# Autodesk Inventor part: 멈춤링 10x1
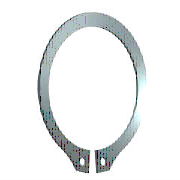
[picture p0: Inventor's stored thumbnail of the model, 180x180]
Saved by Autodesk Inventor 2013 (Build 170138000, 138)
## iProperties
IsCustomPart: 0
Created: 2015-11
Part Number: 멈춤링 10x1
Material: 스테인리스강
Description: 리테이닝 링(C형)
Document SubType Name: Modeling
Standard: KS B 1336
Designer: mdu
Standards Organization: KS
Language: ko-KR
Size Designation: 10 x 1
Categories: <MemberInstance><Categories><Category DisplayName="샤프트 부품" InternalName="7f7aeb1f-a693-4053-b835-cee3144e0d98" Mnemonic="SHFT"><Category DisplayName="써클립" Inter
Density: 8.08 g/cm^3
Mass: 0.434929 g
Surface Area: 1.9243 cm^2
Volume: 0.0538279 cm^3
Author: mdu
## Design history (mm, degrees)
sketch "스케치1"
  geometry: L1 (-6, 0)-(6, 0) reference; L2 (0, 20.189)-(0, -80.536) reference; L3 (-48.09, 0)-(48.09, 0) reference; L4 (-0.3, -9.791)-(-0.3, -12.791); L5 (-0.3, -6.54)-(-0.3, -13.29); L6 (-2.795, 1.6)-(3.672, 1.6); L7 (0.3, -6.54)-(0.3, -13.29); L8 (0.3, -9.791)-(0.3, -12.791); C1 r 0.6 at (-1.2, -11.486); C2 r 0.6 at (1.2, -11.486); A1 r 4.8 centre (0, -5) between (0.3, -9.791) and (-0.3, -9.791); A2 r 6.2 centre (0, -4.6) between (2.988, -10.033) and (-2.988, -10.033); A3 r 7.796 centre (0, -5) between (-1.418, -12.666) and (-0.3, -12.791); A4 r 1.2 centre (-1.2, -11.486) between (-2.383, -11.285) and (-1.418, -12.666); A5 r 1.2 centre (-3.566, -11.084) between (-2.383, -11.285) and (-2.988, -10.033); A6 r 1.2 centre (3.566, -11.084) between (2.988, -10.033) and (2.383, -11.285); A7 r 1.2 centre (1.2, -11.486) between (1.418, -12.666) and (2.383, -11.285); A8 r 7.796 centre (0, -5) between (0.3, -12.791) and (1.418, -12.666)
  constraints: 16 point on circle, 12 end point, 10 centre point, 9 symmetric about line, 5 point on line, 4 tangent, 3 coincident, 2 horizontal, 1 perpendicular, 1 vertical, 5 other
  dimensions: "d0" = 9.6 diameter of A1 (= ND); "d1" = 3 distance of L4.end L4.start (= SRB2); "d6" = 0.3 distance between parallel lines of L2 L5 (= 0.25 x SD5); "d7" = 1.6 distance between parallel lines of L6 L3 (= SRB1); "d8" = 0.4 distance of A1.centre A2.centre (= 0.25 x SRB1); "d9" = 1.2 radius of A4 (= SD5); "d10" = 1.2 radius of A5 (= SD5); "d11" = 0.9 distance from line of L4 A4.centre (= 0.75 x SD5); "d12" = 1.2 diameter of C1 (= SD5); "d13" = 1.2 diameter of C2 (= SD5); "d14" = 5 distance from line of A1.centre L1 (= 0.5 x WD)
extrude "본체" new body sketch "스케치1" distance "d2" = 1 (= SD); taper "d3" = 0 deg
workaxis "Work Axis1"
workplane "Work Plane1"
body "Solid1"
other parameters: "SD" = 1 [user parameter; used in 1 equation term], "SRB1" = 1.6 [user parameter; used in 2 equation terms], "ND" = 9.6 [user parameter; used in 1 equation term], "SRB2" = 3 [user parameter; used in 1 equation term], "SD5" = 1.2 [user parameter; used in 6 equation terms], "d15" = 0, "d16" = 0, "d17" = 0, "d41" = 0, "d42" = 0, "SD3" = 9.3 [user parameter], "WDMAX" = 11 [user parameter]
